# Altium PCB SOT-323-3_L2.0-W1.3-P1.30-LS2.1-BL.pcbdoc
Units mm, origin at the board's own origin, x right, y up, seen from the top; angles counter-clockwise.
Board outline 14.92 x 15.16 mm, 2 copper layers (Top Layer, Bottom Layer), stack 0 mm thick; 1 components, 0 nets, 3 pads, 0 vias.
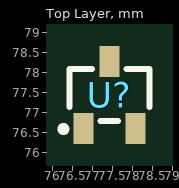
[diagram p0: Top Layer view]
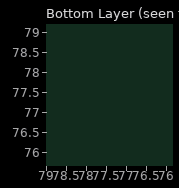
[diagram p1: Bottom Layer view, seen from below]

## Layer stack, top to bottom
Top Layer: signal copper (thickness not stored)
Bottom Layer: signal copper (thickness not stored)

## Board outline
84.775,69.85 69.85,69.85 69.85,85.01 84.775,85.01

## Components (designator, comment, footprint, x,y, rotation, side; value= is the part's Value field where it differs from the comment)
U? "" SOT-323-3_L2.0-W1.3-P1.30-LS2.1-BL 77.425,77.43 r0 top

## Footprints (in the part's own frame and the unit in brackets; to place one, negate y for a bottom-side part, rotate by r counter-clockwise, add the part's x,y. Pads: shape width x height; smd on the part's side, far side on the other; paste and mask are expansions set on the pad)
SOT-323-3_L2.0-W1.3-P1.30-LS2.1-BL [mm]
  rect 0.5x0.78 smd: 1(-0.65,-0.84) 2(0.65,-0.84) 3(0,0.84)
  silkscreen extent -1.22,-0.93 1,0.65

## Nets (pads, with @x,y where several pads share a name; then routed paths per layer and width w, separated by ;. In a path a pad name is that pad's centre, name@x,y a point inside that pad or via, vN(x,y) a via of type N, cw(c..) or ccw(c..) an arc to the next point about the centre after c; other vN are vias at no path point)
pads on no net: U?.1 U?.2 U?.3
